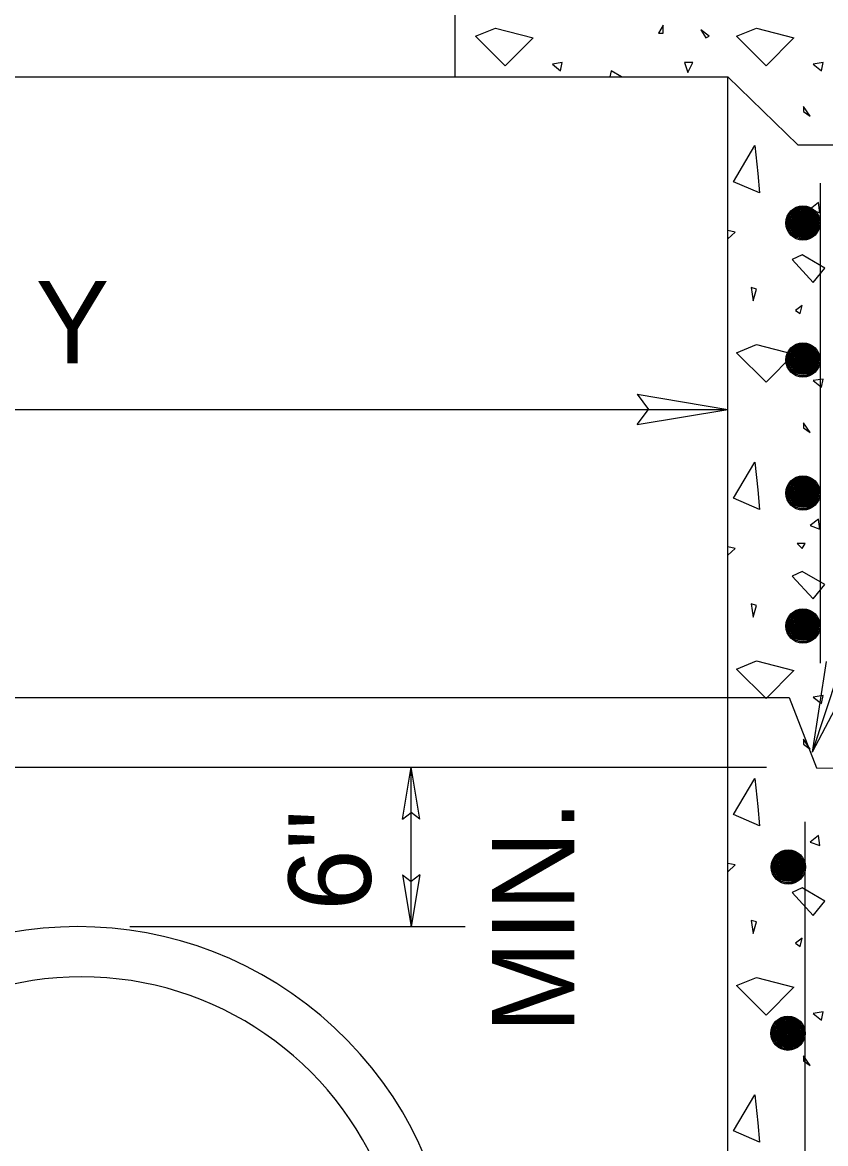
# Model space of a CAD drawing. Extents: x 5.8 to 18, y -5.2 to 5.4.
# Drawn here: x 7.421 to 8.006, y -1.516 to -0.7 of the extents above; entities that cross this region are included whole.
import ezdxf

# ---------------------------------------------------------------- set-up
doc = ezdxf.new("R2010")
doc.units = 0
for name, color, linetype in [('DETL-DIMS', 7, 'Continuous'), ('DETL-LINE', 7, 'Continuous'), ('DETL-NOTE', 7, 'Continuous'), ('DETL-PATT', 7, 'Continuous')]:
    doc.layers.add(name, color=color, linetype=linetype)

msp = doc.modelspace()

# ---------------------------------------------------------------- linework, layer by layer
at = {"layer": 'DETL-DIMS'}
for p, q in [((8.08757, -0.95224), (7.99592, -1.23102)), ((7.86847, -0.97048), (7.93435, -0.98146)), ((7.86847, -0.97048), (7.87671, -0.98146)), ((7.00843, -0.98146), (7.93435, -0.98146)), ((7.86847, -0.99244), (7.93435, -0.98146)), ((7.86847, -0.99244), (7.87671, -0.98146)), ((8.00608, -1.16502), (7.99592, -1.23102)), ((8.02694, -1.17185), (7.99592, -1.23102)), ((7.69765, -1.27977), (7.70392, -1.24212)), ((7.70392, -1.35812), (7.70392, -1.24212)), ((7.7102, -1.27977), (7.70392, -1.24212)), ((7.69765, -1.27977), (7.70392, -1.27506)), ((7.7102, -1.27977), (7.70392, -1.27506)), ((7.69765, -1.32048), (7.70392, -1.35812)), ((7.69765, -1.32048), (7.70392, -1.32518)), ((7.7102, -1.32048), (7.70392, -1.35812)), ((7.7102, -1.32048), (7.70392, -1.32518)), ((7.49902, -1.35812), (7.74314, -1.35812))]:
    msp.add_line(p, q, dxfattribs=at)
at = {"layer": 'DETL-LINE'}
for p, q in [((7.73561, -0.64173), (7.73561, -0.73934)), ((7.00843, -0.73934), (7.93435, -0.73934)), ((7.93435, -1.97495), (7.93435, -0.73934)), ((7.98533, -0.78891), (7.93435, -0.73934)), ((7.98533, -0.78891), (8.0651, -0.78891)), ((8.00161, -0.81687), (8.00161, -1.16632)), ((6.95494, -1.19118), (7.97922, -1.19118)), ((7.97922, -1.19118), (7.9991, -1.24255)), ((6.97208, -1.24212), (7.96267, -1.24212)), ((7.9991, -1.24255), (8.06576, -1.24291)), ((7.99071, -2.02593), (7.99071, -1.28177))]:
    msp.add_line(p, q, dxfattribs=at)
for centre, radius in [((7.98914, -0.84573), 0.01247), ((7.98904, -0.84563), 0.01163), ((7.98792, -0.84563), 0.01009), ((7.98917, -0.84592), 0.01122), ((7.98951, -0.84645), 0.011), ((7.98945, -0.84606), 0.01024), ((7.98833, -0.84514), 0.00834), ((7.98972, -0.84612), 0.00969), ((7.9898, -0.84639), 0.00918), ((7.98813, -0.84612), 0.00724), ((7.98994, -0.84653), 0.00876), ((7.9898, -0.84674), 0.00835), ((7.98751, -0.84653), 0.00578), ((7.99002, -0.84674), 0.00814), ((7.98986, -0.84661), 0.00786), ((7.99021, -0.8468), 0.00751), ((7.99029, -0.84666), 0.00704), ((7.99035, -0.84659), 0.00655), ((7.99035, -0.84645), 0.006), ((7.98847, -0.84625), 0.00467), ((7.99043, -0.84661), 0.00565), ((7.99043, -0.84666), 0.0051), ((7.99064, -0.8471), 0.00488), ((7.99076, -0.84715), 0.00445), ((7.99076, -0.84704), 0.0039), ((7.99092, -0.84694), 0.00377), ((7.99092, -0.84729), 0.00347), ((7.99105, -0.84702), 0.00333), ((7.99111, -0.8471), 0.00285), ((7.99092, -0.84688), 0.00238), ((7.99119, -0.84717), 0.00212), ((7.99127, -0.84715), 0.00175), ((7.99141, -0.84723), 0.00133), ((7.99141, -0.8471), 0.00118), ((7.99182, -0.84715), 0.00148), ((7.99139, -0.8471), 0.000769), ((7.99125, -0.8471), 0.000362), ((7.99155, -0.8471), 0.00023), ((7.98914, -0.94557), 0.01247), ((7.98904, -0.94547), 0.01163), ((7.98792, -0.94547), 0.01009), ((7.98917, -0.94576), 0.01122), ((7.98951, -0.94629), 0.011), ((7.98945, -0.9459), 0.01024), ((7.98833, -0.94498), 0.00834), ((7.98972, -0.94596), 0.00969), ((7.9898, -0.94623), 0.00918), ((7.98813, -0.94596), 0.00724), ((7.98994, -0.94637), 0.00876), ((7.9898, -0.94659), 0.00835), ((7.99002, -0.94659), 0.00814), ((7.98986, -0.94645), 0.00786), ((7.98751, -0.94637), 0.00578), ((7.99021, -0.94665), 0.00751), ((7.99029, -0.94651), 0.00704), ((7.99035, -0.94643), 0.00655), ((7.98847, -0.9461), 0.00467), ((7.99035, -0.94629), 0.006), ((7.99043, -0.94645), 0.00565), ((7.99043, -0.94651), 0.0051), ((7.99064, -0.94694), 0.00488), ((7.99076, -0.947), 0.00445), ((7.99076, -0.94688), 0.0039), ((7.99092, -0.94678), 0.00377), ((7.99092, -0.94714), 0.00347), ((7.99105, -0.94686), 0.00333), ((7.99111, -0.94694), 0.00285), ((7.99092, -0.94672), 0.00238), ((7.99119, -0.94702), 0.00212), ((7.99127, -0.947), 0.00175), ((7.99141, -0.94708), 0.00133), ((7.99141, -0.94694), 0.00118), ((7.99182, -0.947), 0.00148), ((7.99139, -0.94694), 0.000769), ((7.99125, -0.94694), 0.000362), ((7.99155, -0.94694), 0.00023), ((7.98914, -1.0424), 0.01247), ((7.98904, -1.04229), 0.01163), ((7.98792, -1.04229), 0.01009), ((7.98917, -1.04259), 0.01122), ((7.98951, -1.04312), 0.011), ((7.98945, -1.04272), 0.01024), ((7.98833, -1.0418), 0.00834), ((7.98972, -1.04278), 0.00969), ((7.9898, -1.04306), 0.00918), ((7.98813, -1.04278), 0.00724), ((7.98994, -1.04319), 0.00876), ((7.9898, -1.04341), 0.00835), ((7.99002, -1.04341), 0.00814), ((7.98986, -1.04327), 0.00786), ((7.99021, -1.04347), 0.00751), ((7.99029, -1.04333), 0.00704), ((7.99035, -1.04325), 0.00655), ((7.98751, -1.04319), 0.00578), ((7.98847, -1.04292), 0.00467), ((7.99035, -1.04312), 0.006), ((7.99043, -1.04327), 0.00565), ((7.99043, -1.04333), 0.0051), ((7.99064, -1.04376), 0.00488), ((7.99076, -1.04382), 0.00445), ((7.99076, -1.0437), 0.0039), ((7.99092, -1.04361), 0.00377), ((7.99092, -1.04396), 0.00347), ((7.99105, -1.04368), 0.00333), ((7.99111, -1.04376), 0.00285), ((7.99092, -1.04355), 0.00238), ((7.99119, -1.04384), 0.00212), ((7.99127, -1.04382), 0.00175), ((7.99141, -1.0439), 0.00133), ((7.99141, -1.04376), 0.00118), ((7.99182, -1.04382), 0.00148), ((7.99139, -1.04376), 0.000769), ((7.99125, -1.04376), 0.000362), ((7.99155, -1.04376), 0.00023), ((7.98914, -1.13922), 0.01247), ((7.98904, -1.13912), 0.01163), ((7.98792, -1.13912), 0.01009), ((7.98917, -1.13941), 0.01122), ((7.98951, -1.13994), 0.011), ((7.98945, -1.13955), 0.01024), ((7.98833, -1.13863), 0.00834), ((7.98972, -1.13961), 0.00969), ((7.9898, -1.13988), 0.00918), ((7.98813, -1.13961), 0.00724), ((7.98994, -1.14002), 0.00876), ((7.9898, -1.14023), 0.00835), ((7.98751, -1.14002), 0.00578), ((7.99002, -1.14023), 0.00814), ((7.98986, -1.1401), 0.00786), ((7.99021, -1.14029), 0.00751), ((7.99029, -1.14015), 0.00704), ((7.99035, -1.14008), 0.00655), ((7.99035, -1.13994), 0.006), ((7.99043, -1.1401), 0.00565), ((7.98847, -1.13974), 0.00467), ((7.99043, -1.14015), 0.0051), ((7.99064, -1.14059), 0.00488), ((7.99076, -1.14065), 0.00445), ((7.99076, -1.14053), 0.0039), ((7.99092, -1.14043), 0.00377), ((7.99092, -1.14078), 0.00347), ((7.99105, -1.14051), 0.00333), ((7.99111, -1.14059), 0.00285), ((7.99092, -1.14037), 0.00238), ((7.99119, -1.14066), 0.00212), ((7.99127, -1.14065), 0.00175), ((7.99141, -1.14072), 0.00133), ((7.99141, -1.14059), 0.00118), ((7.99182, -1.14065), 0.00148), ((7.99139, -1.14059), 0.000769), ((7.99125, -1.14059), 0.000362), ((7.99155, -1.14059), 0.00023), ((7.97844, -1.31472), 0.01247), ((7.97833, -1.31461), 0.01163), ((7.97722, -1.31461), 0.01009), ((7.97847, -1.31491), 0.01122), ((7.9788, -1.31544), 0.011), ((7.97875, -1.31504), 0.01024), ((7.97763, -1.31412), 0.00834), ((7.97902, -1.3151), 0.00969), ((7.9791, -1.31538), 0.00918), ((7.97743, -1.3151), 0.00724), ((7.97924, -1.31551), 0.00876), ((7.9791, -1.31573), 0.00835), ((7.9768, -1.31551), 0.00578), ((7.97931, -1.31573), 0.00814), ((7.97916, -1.31559), 0.00786), ((7.97951, -1.31579), 0.00751), ((7.97959, -1.31565), 0.00704), ((7.97776, -1.31524), 0.00467), ((7.97965, -1.31557), 0.00655), ((7.97965, -1.31544), 0.006), ((7.97973, -1.31559), 0.00565), ((7.97973, -1.31565), 0.0051), ((7.97994, -1.31608), 0.00488), ((7.98006, -1.31614), 0.00445), ((7.98006, -1.31602), 0.0039), ((7.98022, -1.31593), 0.00377), ((7.98022, -1.31628), 0.00347), ((7.98035, -1.316), 0.00333), ((7.98041, -1.31608), 0.00285), ((7.98022, -1.31587), 0.00238), ((7.98049, -1.31616), 0.00212), ((7.98057, -1.31614), 0.00175), ((7.98071, -1.31622), 0.00133), ((7.98071, -1.31608), 0.00118), ((7.98112, -1.31614), 0.00148), ((7.98069, -1.31608), 0.000769), ((7.98055, -1.31608), 0.000362), ((7.98084, -1.31608), 0.00023), ((7.97824, -1.43573), 0.01247), ((7.97813, -1.43563), 0.01163), ((7.97702, -1.43563), 0.01009), ((7.97827, -1.43592), 0.01122), ((7.9786, -1.43645), 0.011), ((7.97855, -1.43606), 0.01024), ((7.97743, -1.43514), 0.00834), ((7.97882, -1.43612), 0.00969), ((7.9789, -1.43639), 0.00918), ((7.97904, -1.43653), 0.00876), ((7.9789, -1.43674), 0.00835), ((7.97911, -1.43674), 0.00814), ((7.97723, -1.43612), 0.00724), ((7.9766, -1.43653), 0.00578), ((7.97896, -1.43661), 0.00786), ((7.97931, -1.4368), 0.00751), ((7.97939, -1.43666), 0.00704), ((7.97756, -1.43625), 0.00467), ((7.97945, -1.43659), 0.00655), ((7.97945, -1.43645), 0.006), ((7.97953, -1.43661), 0.00565), ((7.97953, -1.43666), 0.0051), ((7.97974, -1.4371), 0.00488), ((7.97986, -1.43715), 0.00445), ((7.97986, -1.43704), 0.0039), ((7.98002, -1.43694), 0.00377), ((7.98002, -1.43729), 0.00347), ((7.98015, -1.43702), 0.00333), ((7.98021, -1.4371), 0.00285), ((7.98002, -1.43688), 0.00238), ((7.98029, -1.43717), 0.00212), ((7.98037, -1.43715), 0.00175), ((7.98051, -1.43723), 0.00133), ((7.98051, -1.4371), 0.00118), ((7.98092, -1.43715), 0.00148), ((7.98049, -1.4371), 0.000769), ((7.98035, -1.4371), 0.000362), ((7.98064, -1.4371), 0.00023)]:
    msp.add_circle(centre, radius, dxfattribs=at)
for centre, radius, start, end in [((7.461, -1.63265), 0.27454, 321.09641, 218.89267), ((7.46386, -1.6306), 0.23592, 312.23829, 227.67559)]:
    msp.add_arc(centre, radius, start, end, dxfattribs=at)
at = {"layer": 'DETL-PATT'}
for points in [[(7.88745, -0.70161), (7.88404, -0.70757), (7.88745, -0.70757)], [(7.76518, -0.70389), (7.79259, -0.71095), (7.77224, -0.73126), (7.75078, -0.70981)], [(7.91851, -0.71095), (7.92075, -0.70981), (7.91482, -0.70502)], [(7.95522, -0.70389), (7.98259, -0.71095), (7.96227, -0.73126), (7.94082, -0.70981)], [(7.80671, -0.73016), (7.81263, -0.73495), (7.81376, -0.72902)], [(7.90298, -0.72902), (7.90522, -0.73608), (7.9089, -0.72902)], [(7.99671, -0.73016), (8.00263, -0.73495), (8.00376, -0.72902)], [(7.98965, -0.76091), (7.98965, -0.76459), (7.99447, -0.76797)], [(7.95635, -0.80977), (7.95745, -0.82389), (7.93855, -0.81569), (7.95408, -0.78946)], [(8.00039, -0.83095), (7.99447, -0.83573), (8.00153, -0.83828)], [(7.98486, -0.84875), (7.98851, -0.8524), (7.99078, -0.84875)], [(7.98118, -0.87244), (7.99671, -0.8891), (8.00518, -0.87867), (7.98851, -0.86906)], [(7.95153, -0.89279), (7.95294, -0.9024), (7.95522, -0.89393)], [(7.98373, -0.90946), (7.9871, -0.91169), (7.98851, -0.90577)], [(7.95522, -0.93428), (7.98259, -0.94134), (7.96227, -0.96169), (7.94082, -0.9402)], [(7.99671, -0.96055), (8.00263, -0.96534), (8.00376, -0.95942)], [(7.98965, -0.99134), (7.98965, -0.99498), (7.99447, -0.9984)], [(7.95635, -1.04016), (7.95745, -1.05428), (7.93855, -1.04608), (7.95408, -1.01985)], [(8.00039, -1.06134), (7.99447, -1.06616), (8.00153, -1.06867)], [(7.98486, -1.07914), (7.98851, -1.08279), (7.99078, -1.07914)], [(7.98118, -1.10287), (7.99671, -1.11949), (8.00518, -1.10906), (7.98851, -1.09946)], [(7.95153, -1.12318), (7.95294, -1.13279), (7.95522, -1.12432)], [(7.98373, -1.13985), (7.9871, -1.14208), (7.98851, -1.13616)], [(7.95522, -1.16467), (7.98259, -1.17173), (7.96227, -1.19208), (7.94082, -1.17063)], [(7.99671, -1.19095), (8.00263, -1.19573), (8.00376, -1.18981)], [(7.98965, -1.22173), (7.98965, -1.22538), (7.99447, -1.22879)], [(7.95635, -1.27055), (7.95745, -1.28467), (7.93855, -1.27651), (7.95408, -1.25024)], [(8.00039, -1.29173), (7.99447, -1.29655), (8.00153, -1.2991)], [(7.98486, -1.30953), (7.98851, -1.31322), (7.99078, -1.30953)], [(7.98118, -1.33326), (7.99671, -1.34993), (8.00518, -1.33946), (7.98851, -1.32985)], [(7.95153, -1.35357), (7.95294, -1.36318), (7.95522, -1.35471)], [(7.98373, -1.37024), (7.9871, -1.37251), (7.98851, -1.36655)], [(7.95522, -1.3951), (7.98259, -1.40216), (7.96227, -1.42248), (7.94082, -1.40102)], [(7.99671, -1.42134), (8.00263, -1.42616), (8.00376, -1.4202)], [(7.98965, -1.45212), (7.98965, -1.45581), (7.99447, -1.45918)], [(7.95635, -1.50098), (7.95745, -1.5151), (7.93855, -1.50691), (7.95408, -1.48063)]]:
    msp.add_lwpolyline(points, close=True, dxfattribs=at)
for points in [[(7.8571, -0.73934), (7.84961, -0.73495), (7.84847, -0.73934)], [(7.93435, -0.8573), (7.93969, -0.8524), (7.93435, -0.85126)], [(7.93435, -1.08769), (7.93969, -1.08279), (7.93435, -1.08169)], [(7.93435, -1.31812), (7.93969, -1.31322), (7.93435, -1.31208)]]:
    msp.add_lwpolyline(points, dxfattribs=at)

# ---------------------------------------------------------------- texts
at = {"layer": 'DETL-NOTE'}
msp.add_text('Y', height=0.06, dxfattribs=at).set_placement((7.43047, -0.94808))
for s, p in [('MIN.', (7.82275, -1.43553)), ('6"', (7.67451, -1.34648))]:
    msp.add_text(s, height=0.06, rotation=90, dxfattribs=at).set_placement(p)

doc.saveas('drawing.dxf')
